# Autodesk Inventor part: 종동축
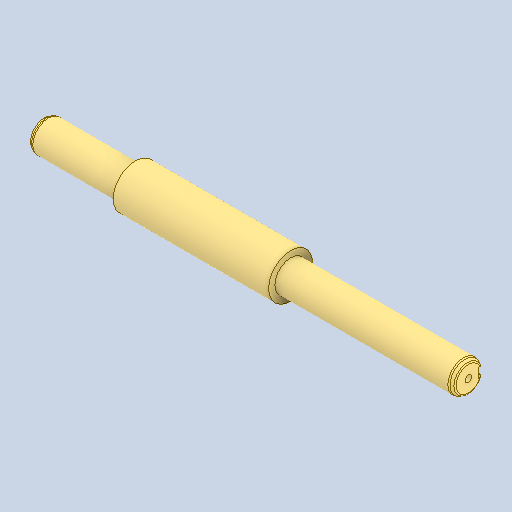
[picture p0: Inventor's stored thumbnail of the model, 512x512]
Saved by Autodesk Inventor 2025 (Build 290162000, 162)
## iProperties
Created: 2026-01
Part Number: 종동축
Material: 강철, 탄소
Document SubType Name: Modeling
Designer: KDI
Density: 7.85 g/cm^3
Appearance: 기본값
Author: jhkim
Sending System: Autodesk Inventor 2026
Preprocessor: ST-DEVELOPER v20.1
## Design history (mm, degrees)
feature "솔리드1"
node "솔리드2"
